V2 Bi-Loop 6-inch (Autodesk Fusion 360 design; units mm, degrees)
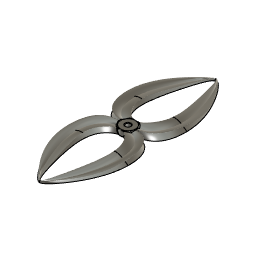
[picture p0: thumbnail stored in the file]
sketch "Hub 5mm Shaft" plane through (0, 0, 0) normal (0, 0, 1) x axis (1, 0, 0)
  circle C1 centre (0, 0) radius 6.5
  circle C2 centre (0, 0) radius 2.5
  point P1 (0, 0)
  point P2 (0, 0)
  point P3 (0, 0)
  coincident P1 P2
  coincident P1 P3
  dimension "d1" diameter C1 = 13
  dimension "d2" diameter C2 = 5
extrude "Extrude1" new body sketch "Hub 5mm Shaft" along normal blind 6 bodies "Hub 5mm Shaft"
sketch "Start Profile" plane through (0, 0, 0) normal (1, 0, 0) x axis (0, 1, 0)
  line L1 (-1.1, 0) -> (0, 0)
  line L2 (-5, 0) -> (-5.9, 0)
  curve K1 (-5, 0) -> (-5.9, 0)
  curve K2 (0, 0) -> (-1.1, 0)
  curve K3 (6.35, 6) -> (5.65, 6)
  curve K4 (0.3, 6) -> (-0.3, 6)
  curve K5 (-1, -1.5) -> (1, 1.5)
  curve K6 (-6, -1.5) -> (-4, 1.5)
  curve K7 (-4.9, 1.5) -> (-6.9, -1.5)
  curve K8 (-0.1, 1.5) -> (-2.1, -1.5)
  point P1 (0, 0)
  point P2 (0, 0)
  point P6 (0, 0)
  point P3 (6, 6)
  point P4 (0, 6)
  point P8 (-5, 0)
  point P5 (-5.9, 0)
  point P7 (-1.1, 0)
  point P9 (5.65, 6)
  point P10 (6.35, 6)
  point P11 (-0.3, 6)
  point P12 (0.3, 6)
  point P21 (0, 0)
  point P24 (0, 0)
  coincident P1 P2
  coincident P1 P6
  horizontal L1
  horizontal L2
  midpoint P3 K3
  midpoint P4 K4
  midpoint P2 K5
  midpoint P8 K6
  midpoint P5 K7
  midpoint P7 K8
  dimension "d5" distance P2 P7 = 1.1
  dimension "d6" distance P5 P8 = 0.9
  dimension "d7" distance P2 P8 = 5
  dimension "d8" distance P4 P5 = 5.9
  dimension "d9" distance P2 P4 = 6
  dimension "d10" distance P2 P3 = 6
  dimension "d11" distance P2 P3 = 6
  dimension "d12" distance P9 P10 = 0.7
  dimension "d13" distance P11 P12 = 0.6
  dimension "d17" distance P21 = 76.2 (= "( 152.4 / 2 ) * 1 mm")
  dimension "d38" distance P24 = 25.4 (= "( 152.4 / 3 / 2 ) * 1 mm")
  dimension "d46" distance P24 = 25.4 (= "( 152.4 / 2 / 3 ) * 1 mm")
sketch "Edge Profile" plane through (0, 0, 0) normal (1, 0, 0) x axis (0, 1, 0)
  line L1 (75.2, 0) -> (76.2, 0)
  curve K1 (75.2, 0) -> (76.2, 0)
  curve K2 (76.2, 1) -> (76.2, -1)
  curve K3 (75.2, -1) -> (75.2, 1)
  curve K4 (75.45, 2) -> (76.05, 2)
  point P2 (76.2, 0)
  point P3 (75.2, 0)
  point P4 (75.75, 2)
  point P9 (0, 0)
  point P10 (76.05, 2)
  point P11 (75.45, 2)
  horizontal L1
  midpoint P2 K2
  midpoint P3 K3
  midpoint P4 K4
  dimension "d14" distance P2 P3 = 1
  dimension "d15" distance P2 P4 = 2
  dimension "d16" distance P2 P4 = 0.45
  dimension "d17" distance P2 P9 = 76.2 (= "( 152.4 / 2 ) * 1 mm")
  dimension "d18" distance P10 P11 = 0.6
sketch "Target Rail" plane through (0, 0, 0) normal (0, 0, 1) x axis (1, 0, 0)
  line L1 (0, -1.1) -> (0, 0)
  line L2 (0, 21.1667) -> (0, 0)
  line L3 (21.1667, 21.1667) -> (0, 21.1667)
  line L4 (-21.1667, 21.1667) -> (0, 21.1667)
  circle C1 centre (0, 0) radius 63.5
  point P1 (0, 0)
  point P2 (0, 0)
  point P5 (0, 0)
  point P6 (0, 21.1667)
  point P7 (21.1667, 21.1667)
  point P8 (-21.1667, 21.1667)
  coincident P1 P2
  coincident P1 P5
  parallel L1 L2
  perpendicular L2 L3
  perpendicular L2 L4
  dimension "d19" diameter C1 = 127
  dimension "d20" distance P5 P6 = 21.1667 (= "( ( 127 / 2 ) / 3 ) * 1 mm")
  dimension "d21" distance P6 P7 = 21.1667 (= "( ( 127 / 2 ) / 3 ) * 1 mm")
  dimension "d22" distance P6 P8 = 21.1667 (= "( 127 / 2 / 3 ) * 1 mm")
work_plane "WorkPlane1" AlongDistance 25.4 (= "( 152.4 / 2 / 3 ) * 1 mm")
sketch "Mid Profile" plane through (0, 25.4, 0) normal (0, 1, 0) x axis (1, 0, 0)
  curve K1 (24.3, 0) -> (25.4, 0)
  curve K2 (23.2177, -2) -> (27.5823, 2)
  curve K3 (13.55, -6) -> (14.25, -6)
  curve K4 (27.1667, 2) -> (21.4333, -2)
  line L1 (24.3, 0) -> (25.4, 0)
  line L2 (13.55, -6) -> (14.25, -6)
  line L3 (-15, 0) -> (-13.9, 0)
  curve K5 (-15, 0) -> (-13.9, 0)
  curve K6 (-16.2542, -2) -> (-11.5458, 2)
  curve K7 (-25.75, -6) -> (-25.05, -6)
  curve K8 (-12.1333, 2) -> (-17.8667, -2)
  point P2 (0, 0)
  point P5 (25.4, 0)
  point P7 (13.9, -6)
  point P3 (14.25, -6)
  point P4 (13.55, -6)
  point P14 (-25.4, -6)
  point P17 (-13.9, 0)
  point P13 (-25.05, -6)
  point P18 (-25.75, -6)
  point P19 (-15, 0)
  point P8 (24.3, 0)
  dimension "d38" distance P2 P5 = 25.4 (= "( 152.4 / 3 / 2 ) * 1 mm")
  dimension "d39" distance P5 P7 = 11.5
  dimension "d40" distance P5 P7 = 6
  dimension "d41" distance P3 P4 = 0.7
  dimension "d42" distance P14 P17 = 11.5
  dimension "d43" distance P14 P17 = 6
  dimension "d44" distance P13 P18 = 0.7
  dimension "d46" distance P2 P14 = 25.4 (= "( 152.4 / 2 / 3 ) * 1 mm")
  dimension "d47" distance P17 P19 = 1.1
  dimension "d84" distance P5 P8 = 1.1
sketch "End Profile" plane through (0, 0, 0) normal (1, 0, 0) x axis (0, 1, 0)
  line L1 (4.7818, 0) -> (5.7818, 0)
  curve K1 (0, 0) -> (0.8, 0)
  curve K2 (-0.2, 1.5) -> (1.8, -1.5)
  curve K3 (-6.25, 6) -> (-5.75, 6)
  curve K4 (1, -1.5) -> (-1, 1.5)
  line L2 (0.8, 0) -> (-0.0182, 0)
  curve K5 (4.7818, 0) -> (5.7818, 0)
  curve K6 (4.8, 1.5) -> (6.8, -1.5)
  curve K7 (-0.2682, 6) -> (0.4318, 6)
  curve K8 (6, -1.5) -> (4, 1.5)
  line L3 (-6.25, 6) -> (-5.75, 6)
  line L4 (-0.2682, 6) -> (0.4318, 6)
  point P2 (0, 0)
  point P11 (0.8, 0)
  point P14 (4.7818, 0)
  point P20 (5.7818, 0)
  point P5 (-0.0182, 0)
  point P6 (-0.0182, 6)
  point P12 (-0.0182, 0)
  point P18 (-6, 6)
  point P7 (-6.25, 6)
  point P23 (-5.75, 6)
  point P3 (0.4318, 6)
  point P17 (-0.2682, 6)
  dimension "d57" distance P2 P11 = 0.8
  dimension "d58" distance P14 P20 = 1
  dimension "d59" distance P5 P20 = 5.8
  dimension "d60" distance P6 P12 = 6
  dimension "d61" distance P6 P20 = 5.8
  dimension "d62" distance P11 P18 = 6.8
  dimension "d63" distance P2 P7 = 6
  dimension "d65" distance P7 P23 = 0.5
  dimension "d66" distance P3 P17 = 0.7
  dimension "d67" distance P6 P17 = 0.25
sketch "Lower Rails" plane through (0, 0, 0) normal (0, 0, 1) x axis (1, 0, 0)
  curve K1 (0, 4.7818) -> (0, -1.1)
  curve K2 (0, 0) -> (0, 5.7818)
  curve K3 (-8, 0) -> (8, 0)
  curve K4 (10, -1) -> (-10, -1.2)
  curve K5 (-3, 5.7818) -> (3, 5.7818)
  curve K6 (3, 4.7818) -> (-3, 4.7818)
  curve K7 (-14.0537, 35.3672) -> (-13.7463, 15.4328)
  curve K8 (-14.8463, 15.4328) -> (-15.1537, 35.3672)
  curve K9 (-2, 76.2) -> (2, 76.2)
  curve K10 (1.7, 75.2) -> (-1.7, 75.2)
  curve K11 (25.2333, 35) -> (25.5667, 15.8)
  curve K12 (24.8667, 15.8) -> (23.7333, 35)
  point P2 (0, -1.1)
  point P7 (0, -1.1)
  point P3 (25.4, 25.4)
  point P8 (25.4, 25.4)
  point P4 (0, 76.2)
  point P9 (0, 76.2)
  point P5 (-15, 25.4)
  point P10 (-15, 25.4)
  point P11 (0, 5.7818)
  point P16 (0, 5.7818)
  point P12 (-13.9, 25.4)
  point P17 (-13.9, 25.4)
  point P13 (0, 75.2)
  point P18 (0, 75.2)
  point P14 (24.3, 25.4)
  point P19 (24.3, 25.4)
  point P1 (0, 0)
  point P15 (0, 0)
  point P6 (0, 4.7818)
  point P36 (0, 4.7818)
  coincident P2 P7
  coincident P3 P8
  coincident P4 P9
  coincident P5 P10
  coincident P11 P16
  coincident P12 P17
  coincident P13 P18
  coincident P14 P19
  coincident P1 P15
  midpoint P15 K3
  midpoint P2 K4
  midpoint P11 K5
  midpoint P6 K6
  midpoint P12 K7
  midpoint P5 K8
  parallel K7 K8
  midpoint P4 K9
  midpoint P13 K10
  coincident P6 P36
  midpoint P3 K11
  midpoint P14 K12
work_plane "WorkPlane2" AlongDistance 6
sketch "Upper Rails" plane through (0, 0, 6) normal (0, 0, 1) x axis (1, 0, 0)
  curve K1 (0, 0) -> (0, 6)
  curve K2 (9.5, -0.3) -> (-9.5, 0.3)
  curve K3 (5, 6) -> (-5, 6)
  curve K4 (14.2818, 33.2093) -> (13.5182, 17.5907)
  curve K5 (-24.9447, 14.9809) -> (-25.8553, 35.8191)
  curve K6 (-1.5, 75.75) -> (1.5, 75.75)
  point P2 (0, 6)
  point P7 (0, 6)
  point P3 (13.9, 25.4)
  point P8 (13.9, 25.4)
  point P5 (-25.4, 25.4)
  point P10 (-25.4, 25.4)
  point P6 (0, 0)
  point P4 (0, 75.75)
  coincident P2 P7
  coincident P3 P8
  coincident P5 P10
  midpoint P6 K2
  midpoint P2 K3
  midpoint P3 K4
  midpoint P5 K5
  midpoint P4 K6
loft "Loft1" sketch "Start Profile" + "Mid Profile" bodies "Template 1 6x3x2"
loft "Loft3" sketch "Mid Profile" + "Edge Profile"
loft "Loft2" sketch "Edge Profile" + "Mid Profile" + "End Profile"
circular_pattern "C-Pattern1" TotalAngle 360 bodies "Template 2 6x3x2"
sketch "Blade Trimmer" plane through (0, 0, 0) normal (0, 0, 1) x axis (1, 0, 0)
  circle C1 centre (0, 0) radius 3
  point P1 (0, 0)
  point P2 (0, 0)
  coincident P1 P2
  dimension "d71" diameter C1 = 6
extrude "Extrude2" cut sketch "Blade Trimmer" along normal blind 14
copy_paste_bodies "CopyPasteBodies1"
chamfer "Start Profile" distance 0.5
offset_faces "OffsetFaces1" distance 2
combine "Start Profile"
fillet "Fillet2" radius 1
offset_faces "OffsetFaces2" distance -2
sketch "Fillet Trimmer" plane through (0, 0, 6) normal (0, 0, 1) x axis (-1, 0, 0)
  arc A1 centre (0, 0) radius 6.5 clockwise from (5.4993, 3.4652) to (6.4615, 0.7061)
  circle C1 centre (0, 0) radius 3
  circle C2 centre (0, 0) radius 7.5
  arc A2 centre (0, 0) radius 6.5 clockwise from (0.8245, 6.4475) to (5.4993, 3.4652)
  arc A3 centre (0, 0) radius 6.5 clockwise from (-6.4615, -0.7061) to (-5.8004, 2.9334)
  arc A4 centre (0, 0) radius 6.5 clockwise from (-5.4993, -3.4652) to (-6.4615, -0.7061)
  arc A5 centre (0, 0) radius 6.5 clockwise from (-0.8245, -6.4475) to (-5.4993, -3.4652)
  arc A6 centre (0, 0) radius 6.5 clockwise from (6.4615, 0.7061) to (5.8004, -2.9334)
  arc A7 centre (0, 0) radius 6.5 clockwise from (-5.8004, 2.9334) to (0.8245, 6.4475)
  arc A8 centre (0, 0) radius 6.5 clockwise from (5.8004, -2.9334) to (-0.8245, -6.4475)
  point P1 (0, 0)
  point P5 (0, 0)
  coincident P1 P5
  dimension "d79" diameter C2 = 15
extrude "Extrude3" cut sketch "Fillet Trimmer" profile of A1 C1 C2 along normal blind 5
mirror "Mirror1" mirrorStitchTolerance 0.1 bodies "6x3x2 CW"
copy_paste_bodies "CopyPasteBodies2"
move "Move1"
circular_pattern "C-Pattern2" TotalAngle 360 bodies "Template 1 6x3x2 (1) (1)"
combine "Combine2" bodies "Template 1 6x3x2 (1) (1)"
scale "Scale1" ScaleX 1.1667 ScaleY 1.1667
copy_paste_bodies "CopyPasteBodies3"
move "Move2"
offset_faces "OffsetFaces3" distance 1
offset_faces "OffsetFaces4" distance 1
combine "Combine3" bodies "Template 1 6x3x2 (1) (1)", "Template 1 6x3x2 (1)"
fillet "Fillet3" radius 1
offset_faces "OffsetFaces5" distance -1
sketch "Sketch14" plane through (0, 0, 7) normal (0, 0, 1) x axis (-1, 0, 0)
  curve K1 (-7.4452, 0.9051) -> (-7.4976, 0.1906)
  curve K2 (-3.4655, -6.6513) -> (-2.7768, -6.967)
  curve K3 (7.4452, -0.9051) -> (7.4976, -0.1906)
  curve K4 (3.4655, 6.6513) -> (2.7768, 6.967)
  circle C1 centre (0, 0) radius 2.5
  arc A1 centre (0, 0) radius 7.5 clockwise from (-7.4452, 0.9051) to (2.7768, 6.967)
  arc A2 centre (0, 0) radius 7.5 clockwise from (-3.4655, -6.6513) to (-7.4976, 0.1906)
  arc A3 centre (0, 0) radius 7.5 clockwise from (7.4452, -0.9051) to (-2.7768, -6.967)
  arc A4 centre (0, 0) radius 7.5 clockwise from (3.4655, 6.6513) to (7.4976, -0.1906)
  circle C2 centre (0, 0) radius 8.5
  concentric C1 C2
  dimension "d106" diameter C2 = 17
extrude "Extrude4" cut sketch "Sketch14" against normal blind 1
chamfer "Start Profile" distance 0.5
mirror "Mirror2" mirrorStitchTolerance 0.1 bodies "7x3x2 CW"
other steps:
base_feature "Base Feature1" bodies "Hub 5mm Shaft", "6x3x2 CCW"
base_feature "Base Feature2" bodies "Template 1 6x3x2", "Template 1 6x3x2 (1)"
base_feature "Base Feature3" bodies "Hub 5mm Shaft (1)", "7x3x2 CCW"
named bodies: "Hub 5mm Shaft", "Template 1 6x3x2", "Template 2 6x3x2", "6x3x2 CCW", "6x3x2 CW", "Template 1 6x3x2 (1)", "Template 1 6x3x2 (1) (1)", "Hub 5mm Shaft (1)", "7x3x2 CCW", "7x3x2 CW"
